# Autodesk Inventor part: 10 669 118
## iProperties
Created: 2006-09
Part Number: 10 669 118
Document SubType Name: Modeling
Designer: Hermsmei
Material: Stahl
Description: Haube
Author: Hermsmei
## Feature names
1. Extrusion1
2. Extrusion2
3. Extrusion3
4. Extrusion4
5. Extrusion7
6. Wandstärke1
7. Extrusion8
8. Extrusion9
9. Extrusion10
10. Bohrung1 [Hole]
